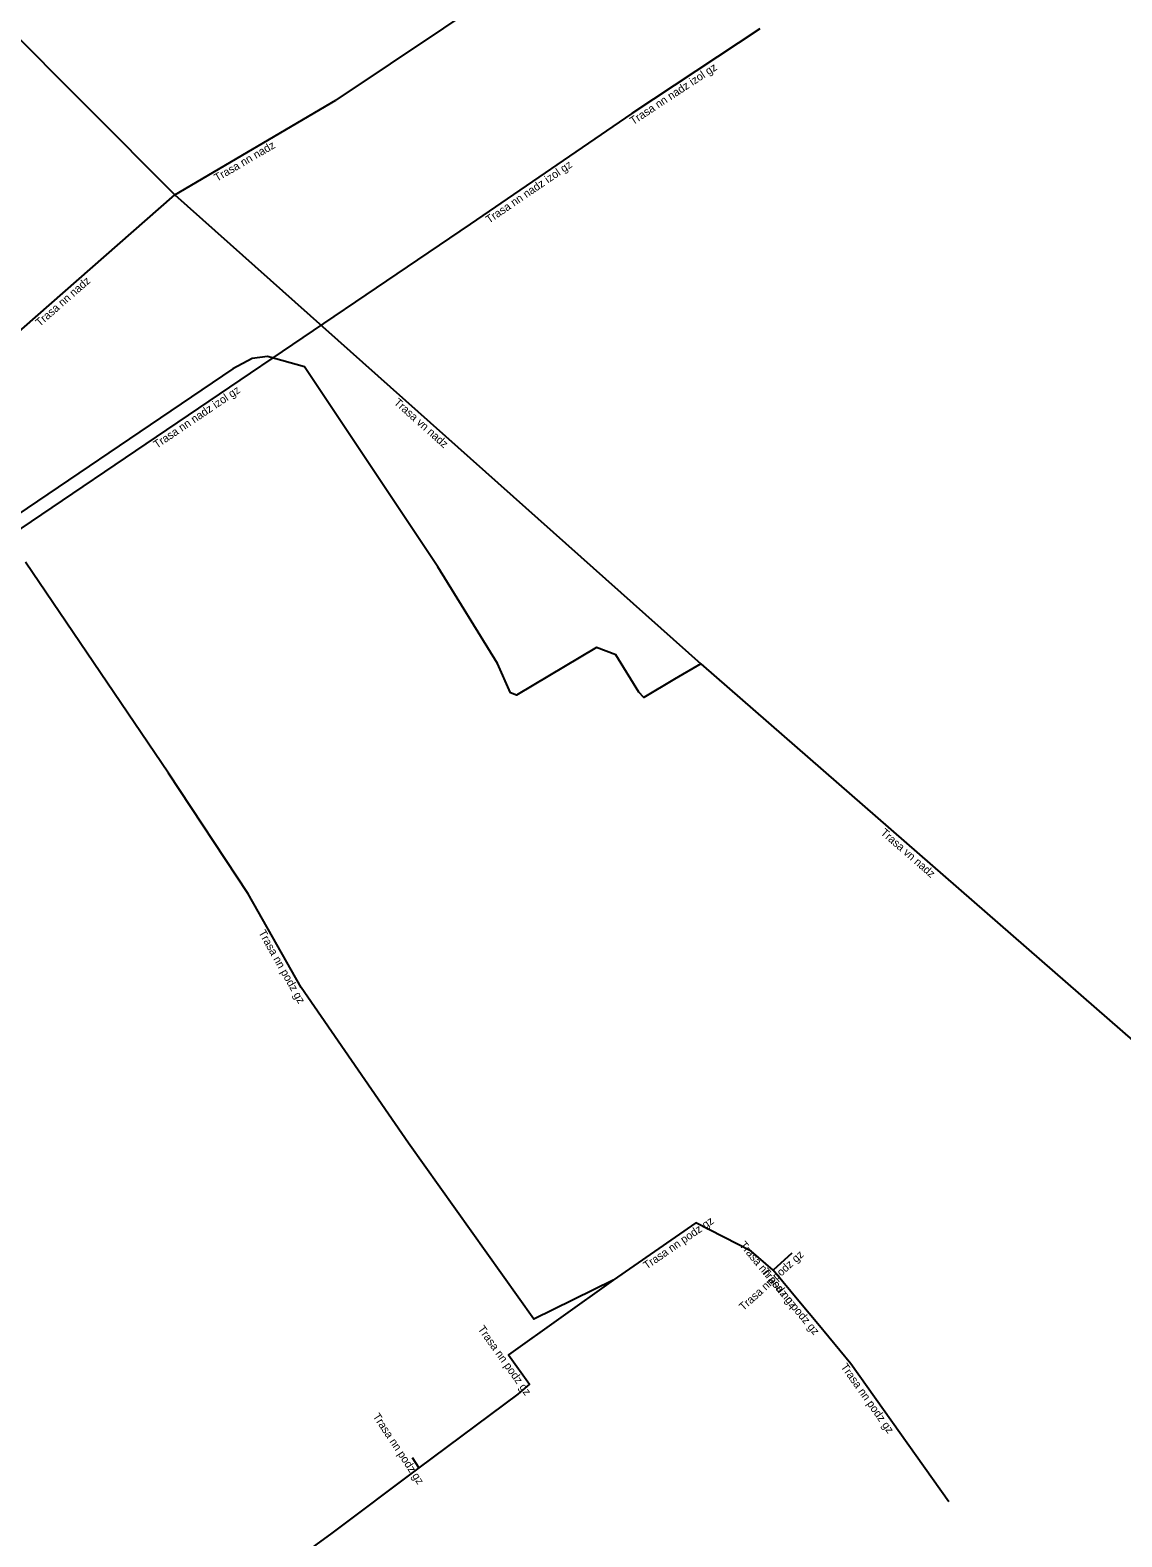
# Model space of a CAD drawing. Extents: x -468149 to -467677, y -1100197 to -1099840.
# Drawn here: x -467861.8 to -467793.5, y -1100020.1 to -1099925.9 of the extents above; entities that cross this region are included whole.
import ezdxf

# ---------------------------------------------------------------- set-up
doc = ezdxf.new("R2010")
doc.units = 0
for name, color, linetype in [('Popiskový text - Ostatní atributy Trasy', 7, 'Continuous'), ('Spojnice NN', 7, 'Continuous'), ('Spojnice VN', 7, 'Continuous')]:
    doc.layers.add(name, color=color, linetype=linetype)

msp = doc.modelspace()

# ---------------------------------------------------------------- linework, layer by layer
at = {"layer": 'Spojnice NN'}
for points in [[(-467822.43, -1099916.76), (-467842.688, -1099930.324)], [(-467816.179, -1099925.87), (-467824.17, -1099931.153)], [(-467852.759, -1099936.229), (-467842.688, -1099930.324)], [(-467824.17, -1099931.153), (-467834.288, -1099938.069)], [(-467865.757, -1099947.633), (-467852.759, -1099936.229)], [(-467834.288, -1099938.069), (-467865.684, -1099959.314)], [(-467825.34, -1100004.08), (-467830.31, -1100006.51), (-467838.14, -1099995.5), (-467844.86, -1099985.77), (-467848.16, -1099979.92), (-467853.15, -1099972.38), (-467862.08, -1099959.19)], [(-467815.35, -1100003.44), (-467816.71, -1100002.25), (-467820.17, -1100000.49), (-467825.34, -1100004.08)], [(-467814.182, -1100002.372), (-467815.35, -1100003.44)], [(-467825.34, -1100004.08), (-467831.89, -1100008.73), (-467830.57, -1100010.58), (-467831.3, -1100011.19), (-467837.5, -1100015.79)], [(-467813.635, -1100005.505), (-467815.35, -1100003.44)], [(-467812.556, -1100006.803), (-467813.635, -1100005.505)], [(-467804.367, -1100017.924), (-467810.49, -1100009.29), (-467812.556, -1100006.803)], [(-467837.92, -1100015.154), (-467837.5, -1100015.79)], [(-467837.5, -1100015.79), (-467842.93, -1100019.89), (-467851.39, -1100026.05)]]:
    msp.add_lwpolyline(points, dxfattribs=at)
at = {"layer": 'Spojnice VN'}
for points in [[(-467852.759, -1099936.229), (-467928.719, -1099859.979)], [(-467852.759, -1099936.229), (-467819.86, -1099965.54)], [(-467819.86, -1099965.54), (-467821.51, -1099966.51), (-467823.432, -1099967.663), (-467823.75, -1099967.32), (-467825.19, -1099964.98), (-467826.38, -1099964.52), (-467831.38, -1099967.51), (-467831.77, -1099967.36), (-467832.58, -1099965.53), (-467836.31, -1099959.48), (-467844.64, -1099946.99), (-467846.96, -1099946.34), (-467847.92, -1099946.47), (-467849.12, -1099947.12), (-467865.88, -1099958.44), (-467884.43, -1099970.92), (-467902.87, -1099983.43), (-467920.29, -1099995.09), (-467929.47, -1100001.36), (-467948.11, -1100013.96)], [(-467819.86, -1099965.54), (-467791.884, -1099989.951)]]:
    msp.add_lwpolyline(points, dxfattribs=at)

# ---------------------------------------------------------------- texts
at = {"layer": 'Popiskový text - Ostatní atributy Trasy'}
for s, rotation, p in [('Trasa nn nadz izol gz', 33.47151, (-467824.1, -1099931.886)), ('Trasa nn nadz', 30.38467, (-467850.11, -1099935.43)), ('Trasa nn nadz izol gz', 34.35329, (-467833.103, -1099938.046)), ('Trasa nn nadz', 41.26081, (-467861.195, -1099944.495)), ('Trasa nn nadz izol gz', 34.086, (-467853.875, -1099952.108)), ('Trasa vn nadz', 318.30091, (-467839.092, -1099949.276)), ('Trasa vn nadz', 318.89305, (-467808.671, -1099976.166)), ('Trasa nn podz gz', 299.42746, (-467847.541, -1099982.342)), ('Trasa nn podz gz', 34.77575, (-467823.246, -1100003.417)), ('Trasa nn podz gz', 42.43928, (-467817.201, -1100006.013)), ('Trasa nn podz gz', 309.71813, (-467817.48, -1100001.893)), ('Trasa nn podz gz', 309.71755, (-467816.083, -1100003.575)), ('Trasa nn podz gz', 305.50837, (-467833.835, -1100007.123)), ('Trasa nn podz gz', 305.33946, (-467811.146, -1100009.488)), ('Trasa nn podz gz', 303.45555, (-467840.399, -1100012.582))]:
    msp.add_text(s, height=0.5, rotation=rotation, dxfattribs=at).set_placement(p)

doc.saveas('drawing.dxf')
